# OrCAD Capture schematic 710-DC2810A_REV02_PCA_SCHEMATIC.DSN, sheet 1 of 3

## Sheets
1 LTM4673 PAGE1: size Custom; company: ANALOG DEVICES; note: DEMO BOARD BILL OF MATERIALS; note: QUAD OUTPUT DC/DC PSM µMODULE REGULATOR
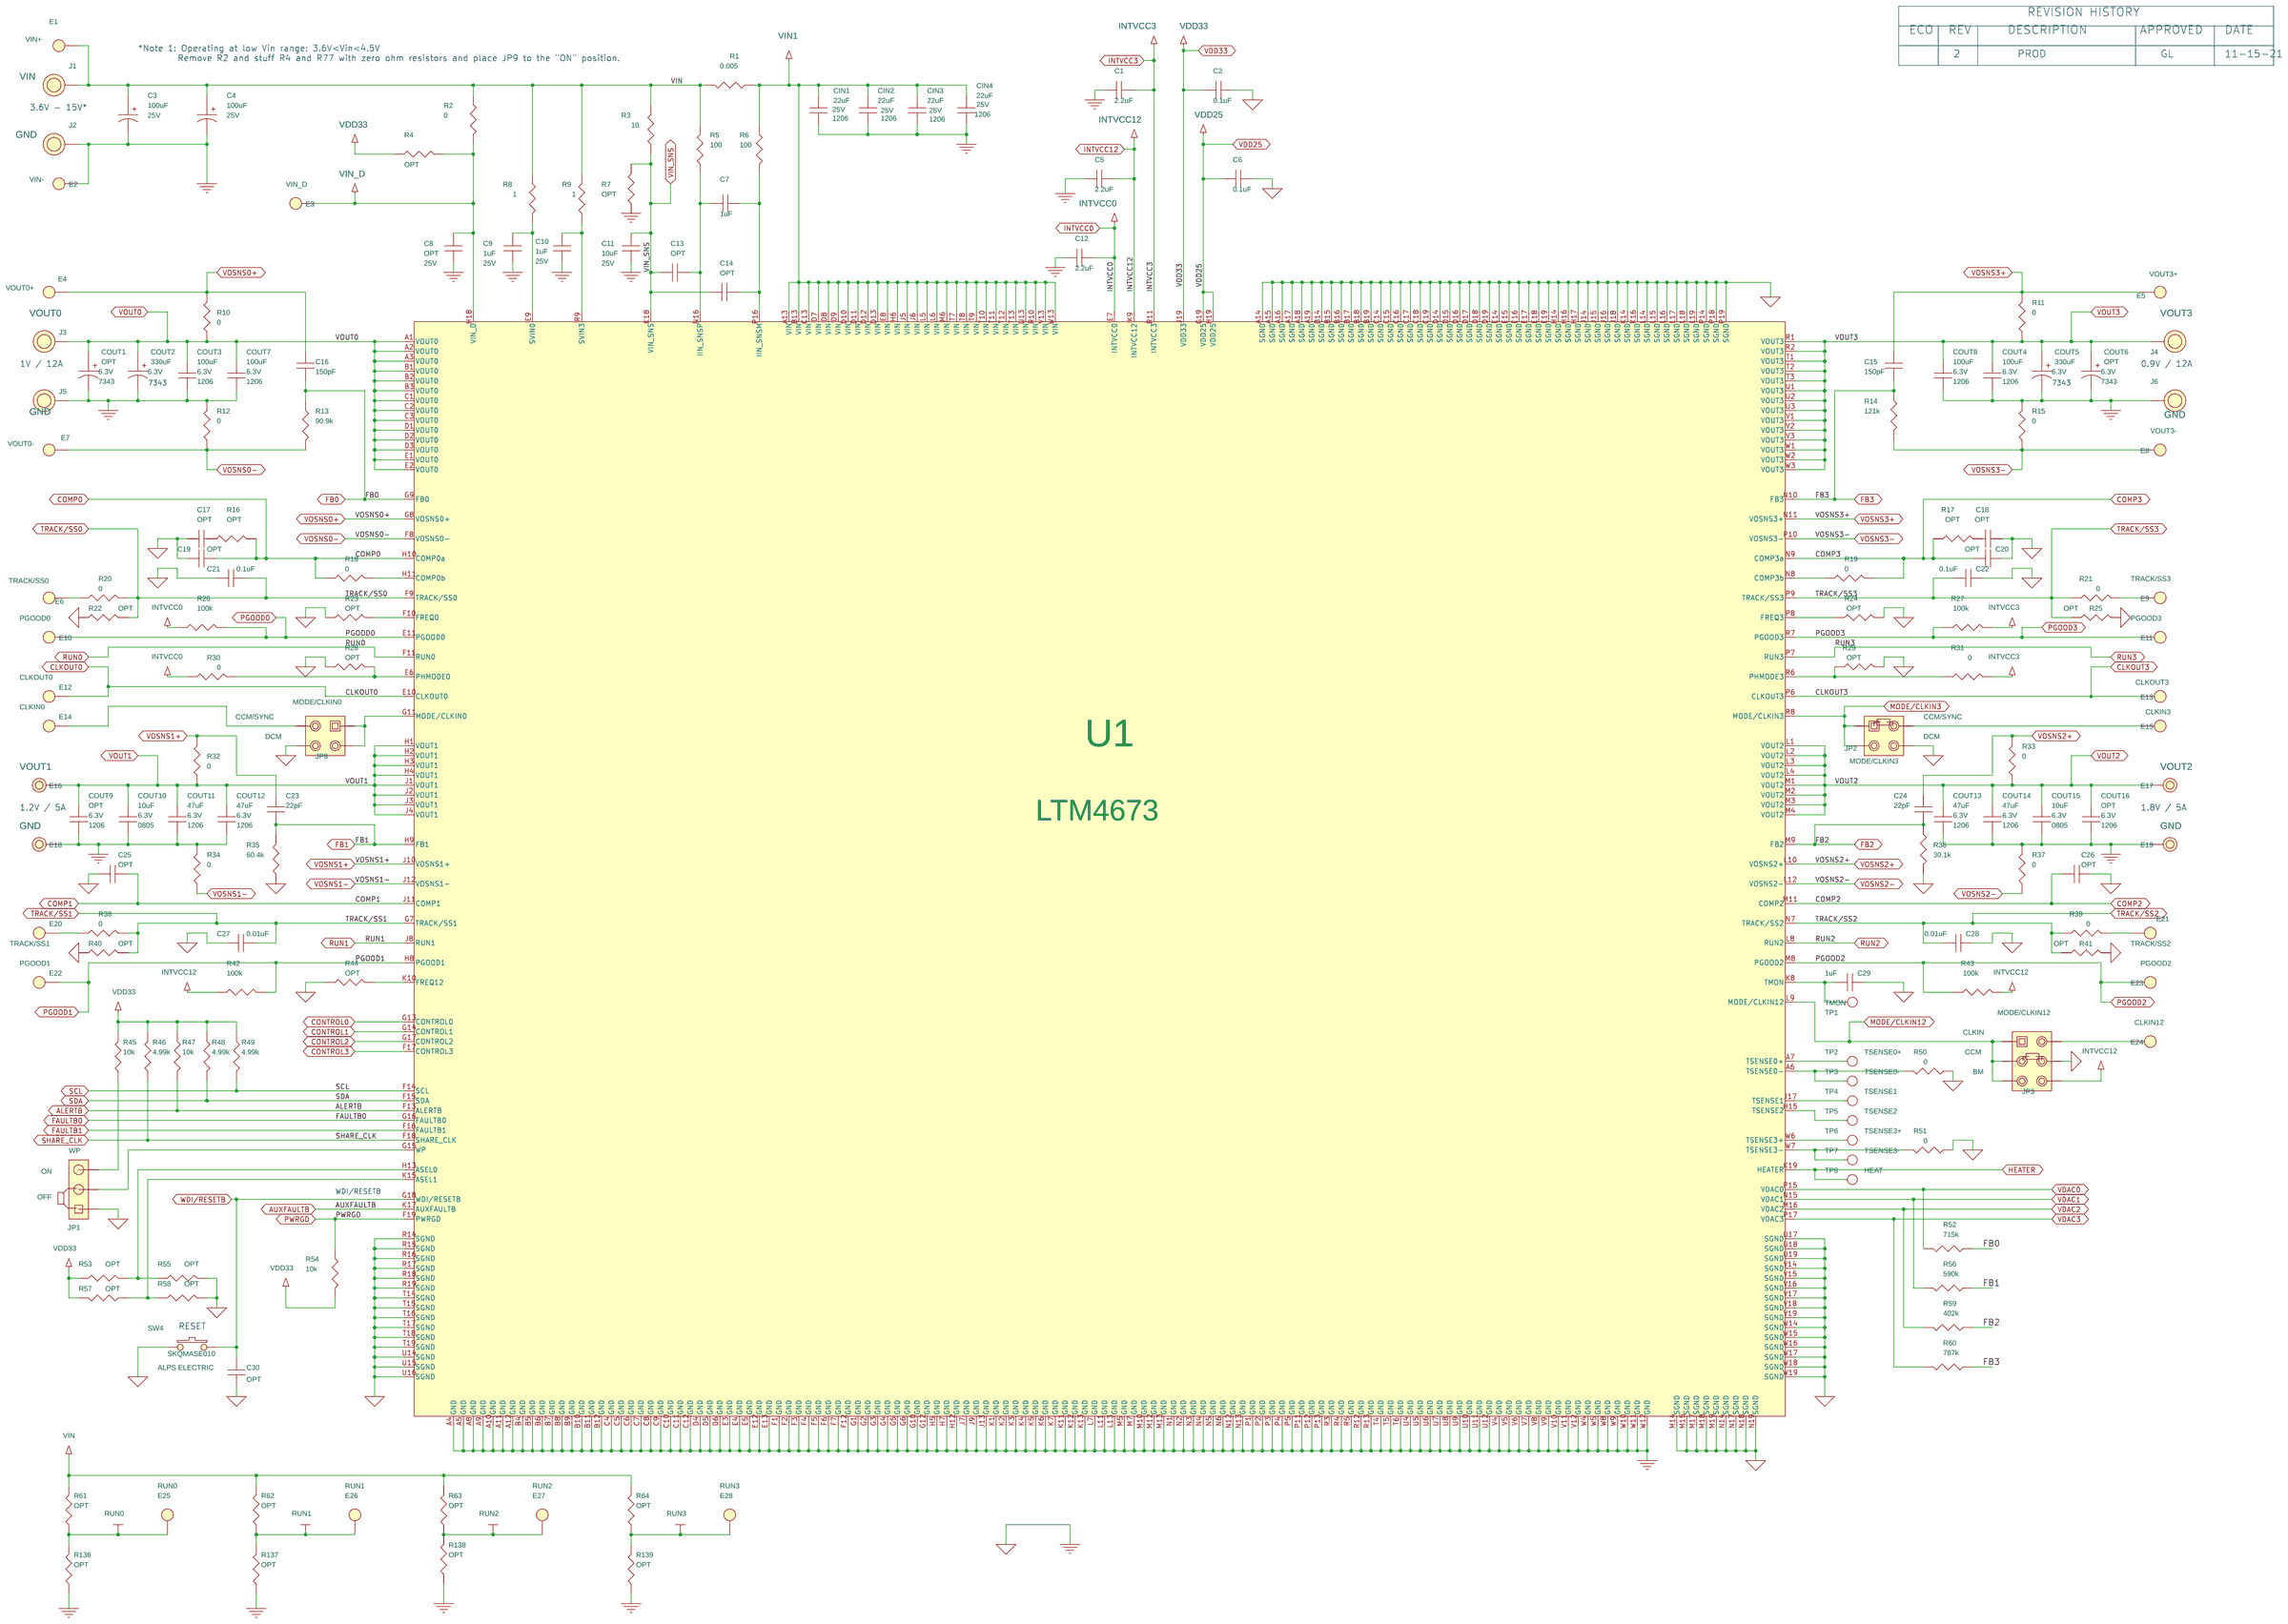
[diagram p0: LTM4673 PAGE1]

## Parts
C1  2.2uF  [CC0603N]
C2  0.1uF  [CC0603N]
C3  100uF  [PANASONIC_SVPF_8X6.9]
C4  100uF  [PANASONIC_SVPF_8X6.9]
C5  2.2uF  [CC0603N]
C6  0.1uF  [CC0603N]
C7  1uF  [CC0603N]
C8  OPT  [CC0603N]
C9  1uF  [CC0603N]
C10  1uF  [CC0603N]
C11  10uF  [CC0603N]
C12  2.2uF  [CC0603N]
C13  OPT  [CC0603N]
C14  OPT  [CC0603N]
C15  150pF  [CC0603N]
C16  150pF  [CC0603N]
C17  OPT  [CC0603N]
C18  OPT  [CC0603N]
C19  OPT  [CC0603N]
C20  OPT  [CC0603N]
C21  0.1uF  [CC0603N]
C22  0.1uF  [CC0603N]
C23  22pF  [CC0603N]
C24  22pF  [CC0603N]
C25  OPT  [CC0603N]
C26  OPT  [CC0603N]
C27  0.01uF  [CC0603N]
C28  0.01uF  [CC0603N]
C29  1uF  [CC0603N]
C30  OPT  [CC0603N]
CIN1  22uF  [CC1206N]
CIN2  22uF  [CC1206N]
CIN3  22uF  [CC1206N]
CIN4  22uF  [CC1206N]
COUT1  OPT  [CAPMP7343N]
COUT2  330uF  [CAPMP7343N]
COUT3  100uF  [CC1206N]
COUT4  100uF  [CC1206N]
COUT5  330uF  [CAPMP7343N]
COUT6  OPT  [CAPMP7343N]
COUT7  100uF  [CC1206N]
COUT8  100uF  [CC1206N]
COUT9  OPT  [CC1206N]
COUT10  10uF  [CC0805N]
COUT11  47uF  [CC1206N]
COUT12  47uF  [CC1206N]
COUT13  47uF  [CC1206N]
COUT14  47uF  [CC1206N]
COUT15  10uF  [CC0805N]
COUT16  OPT  [CC1206N]
E1  TEST POINT  [MILLMAX2308]
E2  TEST POINT  [MILLMAX2308]
E3  TEST POINT  [MILLMAX2308]
E4  TEST POINT  [MILLMAX2308]
E5  TEST POINT  [MILLMAX2308]
E6  TEST POINT  [MILLMAX2308]
E7  TEST POINT  [MILLMAX2308]
E8  TEST POINT  [MILLMAX2308]
E9  TEST POINT  [MILLMAX2308]
E10  TEST POINT  [MILLMAX2308]
E11  TEST POINT  [MILLMAX2308]
E12  TEST POINT  [MILLMAX2308]
E13  TEST POINT  [MILLMAX2308]
E14  TEST POINT  [MILLMAX2308]
E15  TEST POINT  [MILLMAX2308]
E16  TEST POINT  [MILLMAX2501]
E17  TEST POINT  [MILLMAX2501]
E18  TEST POINT  [MILLMAX2501]
E19  TEST POINT  [MILLMAX2501]
E20  TEST POINT  [MILLMAX2308]
E21  TEST POINT  [MILLMAX2308]
E22  TEST POINT  [MILLMAX2308]
E23  TEST POINT  [MILLMAX2308]
E24  TEST POINT  [MILLMAX2308]
E25  TEST POINT  [MILLMAX2308]
E26  TEST POINT  [MILLMAX2308]
E27  TEST POINT  [MILLMAX2308]
E28  TEST POINT  [MILLMAX2308]
J1  BANANA JACK  [KEY-575-4]
J2  BANANA JACK  [KEY-575-4]
J3  BANANA JACK  [KEY-575-4]
J4  BANANA JACK  [KEY-575-4]
J5  BANANA JACK  [KEY-575-4]
J6  BANANA JACK  [KEY-575-4]
JP1  HDR.  [HD1X3-079]
JP2  HDR  [HD2X2-079]
JP3  HDR.  [HD2X3-079]
JP8  HDR  [HD2X2-079]
R1  0.005  [PANASONIC-ERJMS4H]
R2  0  [CR0603N]
R3  10  [CR0603N]
R4  OPT  [CR0603N]
R5  100  [CR0603N]
R6  100  [CR0603N]
R7  OPT  [CR0603N]
R8  1  [CR0603N]
R9  1  [CR0603N]
R10  0  [CR0603N]
R11  0  [CR0603N]
R12  0  [CR0603N]
R13  90.9k  [CR0603N]
R14  121k  [CR0603N]
R15  0  [CR0603N]
R16  OPT  [CR0603N]
R17  OPT  [CR0603N]
R18  0  [CR0603N]
R19  0  [CR0603N]
R20  0  [CR0603N]
R21  0  [CR0603N]
R22  OPT  [CR0603N]
R23  OPT  [CR0603N]
R24  OPT  [CR0603N]
R25  OPT  [CR0603N]
R26  100k  [CR0603N]
R27  100k  [CR0603N]
R28  OPT  [CR0603N]
R29  OPT  [CR0603N]
R30  0  [CR0603N]
R31  0  [CR0603N]
R32  0  [CR0603N]
R33  0  [CR0603N]
R34  0  [CR0603N]
R35  60.4k  [CR0603N]
R36  30.1k  [CR0603N]
R37  0  [CR0603N]
R38  0  [CR0603N]
R39  0  [CR0603N]
R40  OPT  [CR0603N]
R41  OPT  [CR0603N]
R42  100k  [CR0603N]
R43  100k  [CR0603N]
R44  OPT  [CR0603N]
R45  10k  [CR0603N]
R46  4.99k  [CR0603N]
R47  10k  [CR0603N]
R48  4.99k  [CR0603N]
R49  4.99k  [CR0603N]
R50  0  [CR0603N]
R51  0  [CR0603N]
R52  715k  [CR0603N]
R53  OPT  [CR0603N]
R54  10k  [CR0603N]
R55  OPT  [CR0603N]
R56  590k  [CR0603N]
R57  OPT  [CR0603N]
R58  OPT  [CR0603N]
R59  402k  [CR0603N]
R60  787k  [CR0603N]
R61  OPT  [CR0603N]
R62  OPT  [CR0603N]
R63  OPT  [CR0603N]
R64  OPT  [CR0603N]
R136  OPT  [CR0603N]
R137  OPT  [CR0603N]
R138  OPT  [CR0603N]
R139  OPT  [CR0603N]
SW4  SPST  [ALPS-SKQMASE010]
TP1  TMON  [PAD]
TP2  TSENSE0+  [PAD]
TP3  TSENSE0-  [PAD]
TP4  TSENSE1  [PAD]
TP5  TSENSE2  [PAD]
TP6  TSENSE3+  [PAD]
TP7  TSENSE3-  [PAD]
TP8  HEAT  [PAD]
U1  LTM4673  [LTC-BGA-361-1601]
XJP1  SHUNT
XJP2  SHUNT
XJP3  SHUNT
XJP8  SHUNT

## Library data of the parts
C1 C5 C12 = CAP: CAP.,2.2uF,X5R,6.3V,10%,0603; CLASS: DISCRETE; Dielectric Type: X5R; FPLIST: CC0603N,CC0603L,CC0603M; Inventory Qty: 5538; Manufacturer: AVX; Manufacturer PN: 06036D225KAT2A; PART_NUMBER: 150-0116; Package Size: 0603; Rated Voltage: 6.3V; Tolerance: 10%
C2 C6 C21 C22 = CAP: CAP.,0.1uF,X7R,16V,10%,0603,FLEXITERM; CLASS: DISCRETE; Dielectric Type: X7R; FPLIST: CC0603N,CC0603L,CC0603M; Inventory Qty: 23721; Manufacturer: AVX; Manufacturer PN: 0603YC104KAZ2A; PART_NUMBER: 150-0165; Package Size: 0603; Rated Voltage: 16V; Tolerance: 10%
C3 C4 = CAP_P_ALT: CAP.,100uF,ALUM. OS-CON,25V,20%,8x6.9mm SMD, E7,SVPF Series; CLASS: DISCRETE; Component: cap; Dielectric Type: ALUM. OS-CON; Inventory Qty: 6; Manufacturer: PANASONIC; Manufacturer PN: 25SVPF100M; PART_NUMBER: 150-2546; Package Size: 8x6.9mm SMD, E7; Rated Voltage: 25V; Tolerance: 20%; UserField01: SVPF Series
C7 C9 C10 = CAP: CAP.,1uF,X7R,25V,10%,0603,AEC-Q200; CLASS: DISCRETE; Dielectric Type: X7R; FPLIST: CC0603N,CC0603L,CC0603M; Inventory Qty: 14407; Manufacturer: MURATA; Manufacturer PN: GCM188R71E105KA64D; PART_NUMBER: 150-0291; Package Size: 0603; Rated Voltage: 25V; Tolerance: 10%
C8 = CAP: CAP., OPTION, 0603; CLASS: DISCRETE; FPLIST: CC0603N,CC0603L,CC0603M; PART_FIELD_01: 25V; PART_NUMBER: 150-3038; Package Size: 0603; Package Type: SMD; UserField01: OPTION
C11 = CAP: CAP.,10uF,X5R,25V,20%,0603,NO SUBS. ALLOWED; CLASS: DISCRETE; Dielectric Type: X5R; FPLIST: CC0603N,CC0603L,CC0603M; Inventory Qty: 18160; Manufacturer: MURATA; Manufacturer PN: GRM188R61E106MA73D; PART_NUMBER: 150-2347; Package Size: 0603; Rated Voltage: 25V; Tolerance: 20%; UserField01: NO SUBS. ALLOWED
C13 C14 C17-C20 C25 C26 C30 = CAP: CAP., OPTION, 0603; CLASS: DISCRETE; FPLIST: CC0603N,CC0603L,CC0603M; PART_NUMBER: 150-3038; Package Size: 0603; Package Type: SMD; UserField01: OPTION
C15 C16 = CAP: CAP.,150pF,X7R,50V,10%,0603; CLASS: DISCRETE; Dielectric Type: X7R; FPLIST: CC0603N,CC0603L,CC0603M; Inventory Qty: 17421; Manufacturer: AVX; Manufacturer PN: 06035C151KAT2A; PART_NUMBER: 150-2627; Package Size: 0603; Rated Voltage: 50V; Tolerance: 10%; UserField01: OPTION
C23 = CAP: CAP.,22pF,C0G,50V,5%,0603; CLASS: DISCRETE; Dielectric Type: C0G; FPLIST: CC0603N,CC0603L,CC0603M; Inventory Qty: 11643; Manufacturer: AVX; Manufacturer PN: 06035A220JAT2A; PART_NUMBER: 150-2248; Package Size: 0603; Rated Voltage: 50V; Tolerance: 5%
C24 = CAP: CAP.,22pF,C0G,50V,5%,0603; CLASS: DISCRETE; Dielectric Type: C0G; FPLIST: CC0603N,CC0603L,CC0603M; Inventory Qty: 11643; Manufacturer: AVX; Manufacturer PN: 06035A220JAT2A; PART_NUMBER: 150-2248; Package Size: 0603; Rated Voltage: 50V; Tolerance: 5%; UserField01: OPTION
C27 C28 = CAP: CAP.,0.01uF,X7R,16V,10%,0603; CLASS: DISCRETE; Dielectric Type: X7R; FPLIST: CC0603N,CC0603L,CC0603M; Inventory Qty: 69461; Manufacturer: AVX; Manufacturer PN: 0603YC103KAT2A; PART_NUMBER: 150-0038; Package Size: 0603; Rated Voltage: 16V; Tolerance: 10%
C29 = CAP: CAP.,1uF,X7R,16V,10%,0603; CLASS: DISCRETE; Dielectric Type: X7R; FPLIST: CC0603N,CC0603L,CC0603M; Inventory Qty: 29507; Manufacturer: KEMET; Manufacturer PN: C0603C105K4RAC7867; PART_NUMBER: 150-0179; Package Size: 0603; Rated Voltage: 16V; Tolerance: 10%
CIN1-CIN4 = CAP: CAP.,22uF,X5R,25V,10%,1206; CLASS: DISCRETE; Dielectric Type: X5R; FPLIST: CC1206N,CC1206L,CC1206M; Inventory Qty: 8019; Manufacturer: AVX; Manufacturer PN: 12063D226KAT2A; PART_NUMBER: 150-0253; Package Size: 1206; Rated Voltage: 25V; Tolerance: 10%
COUT1 COUT6 = CAP_P_ALT: CAP., OPTION, 7343; BOM Notes: COUT1,COUT6=6.3V; CLASS: DISCRETE; FPLIST: CAPMP7343N,CAPMP7343L,CAPMP7343M; PART_FIELD_01: 6.3V; PART_NUMBER: 150-0067; Package Size: 7343; Package Type: SMD
COUT2 COUT5 = CAP_P_ALT: CAP.,330uF,TANT. POSCAP,6.3V,20%,7343,10mOHMS, TPF, NO SUBS. ALLOWED; CLASS: DISCRETE; Dielectric Type: TANT. POSCAP; FPLIST: CAPMP7343N,CAPMP7343L,CAPMP7343M; Inventory Qty: 4336; Manufacturer: PANASONIC; Manufacturer PN: 6TPF330M9L; PART_NUMBER: 150-3034; Package Size: 7343; Rated Voltage: 6.3V; Tolerance: 20%
COUT3 COUT4 COUT7 COUT8 = CAP: CAP.,100uF,X5R,6.3V,10%,1206; CLASS: DISCRETE; Dielectric Type: X5R; FPLIST: CC1206N,CC1206L,CC1206M; Inventory Qty: 6880; Manufacturer: MURATA; Manufacturer PN: GRM31CR60J107KE39L; PART_NUMBER: 150-2327; Package Size: 1206; Rated Voltage: 6.3V; Tolerance: 10%
COUT9 COUT16 = CAP: CAP., OPTION, 1206; BOM Notes: COUT9,COUT16=6.3V; CLASS: DISCRETE; FPLIST: CC1206N,CC1206L,CC1206M; PART_FIELD_01: 6.3V; PART_NUMBER: 150-3160; Package Size: 1206; Package Type: SMD
COUT10 COUT15 = CAP: CAP.,10uF,X5R,6.3V,10%,0805; CLASS: DISCRETE; Dielectric Type: X5R; FPLIST: CC0805N,CC0805L,CC0805M; Inventory Qty: 29564; Manufacturer: AVX; Manufacturer PN: 08056D106KAT2A; PART_NUMBER: 150-0079; Package Size: 0805; Rated Voltage: 6.3V; Tolerance: 10%
COUT11-COUT14 = CAP: CAP.,47uF,X5R,6.3V,20%,1206; CLASS: DISCRETE; Dielectric Type: X5R; FPLIST: CC1206N,CC1206L,CC1206M; Inventory Qty: 7374; Manufacturer: MURATA; Manufacturer PN: GRM31CR60J476ME19L; PART_NUMBER: 150-3443; Package Size: 1206; Rated Voltage: 6.3V; Tolerance: 20%
E1 = TEST_POINT_.156_MILL-MAX_2308: TEST POINT,TURRET,0.064" MTG. HOLE,PCB 0.062" THK; CLASS: IO; Inventory Qty: 767848; Manufacturer: MILL-MAX; Manufacturer PN: 2308-2-00-80-00-00-07-0; PART_FIELD_01: VIN+; PART_NUMBER: 260-0004
E2 = TEST_POINT_.156_MILL-MAX_2308: TEST POINT,TURRET,0.064" MTG. HOLE,PCB 0.062" THK; CLASS: IO; Inventory Qty: 767848; Manufacturer: MILL-MAX; Manufacturer PN: 2308-2-00-80-00-00-07-0; PART_FIELD_01: VIN-; PART_NUMBER: 260-0004
E3 = TEST_POINT_.156_MILL-MAX_2308: TEST POINT,TURRET,0.064" MTG. HOLE,PCB 0.062" THK; CLASS: IO; Inventory Qty: 767848; Manufacturer: MILL-MAX; Manufacturer PN: 2308-2-00-80-00-00-07-0; PART_FIELD_01: VIN_D; PART_NUMBER: 260-0004
E4 = TEST_POINT_.156_MILL-MAX_2308: TEST POINT,TURRET,0.064" MTG. HOLE,PCB 0.062" THK; CLASS: IO; Inventory Qty: 767848; Manufacturer: MILL-MAX; Manufacturer PN: 2308-2-00-80-00-00-07-0; PART_FIELD_01: VOUT0+; PART_NUMBER: 260-0004
E5 = TEST_POINT_.156_MILL-MAX_2308: TEST POINT,TURRET,0.064" MTG. HOLE,PCB 0.062" THK; CLASS: IO; Inventory Qty: 767848; Manufacturer: MILL-MAX; Manufacturer PN: 2308-2-00-80-00-00-07-0; PART_FIELD_01: VOUT3+; PART_NUMBER: 260-0004
E6 = TEST_POINT_.156_MILL-MAX_2308: TEST POINT,TURRET,0.064" MTG. HOLE,PCB 0.062" THK; CLASS: IO; Inventory Qty: 767848; Manufacturer: MILL-MAX; Manufacturer PN: 2308-2-00-80-00-00-07-0; PART_FIELD_01: TRACK/SS0; PART_NUMBER: 260-0004
E7 = TEST_POINT_.156_MILL-MAX_2308: TEST POINT,TURRET,0.064" MTG. HOLE,PCB 0.062" THK; CLASS: IO; Inventory Qty: 767848; Manufacturer: MILL-MAX; Manufacturer PN: 2308-2-00-80-00-00-07-0; PART_FIELD_01: VOUT0-; PART_NUMBER: 260-0004
E8 = TEST_POINT_.156_MILL-MAX_2308: TEST POINT,TURRET,0.064" MTG. HOLE,PCB 0.062" THK; CLASS: IO; Inventory Qty: 767848; Manufacturer: MILL-MAX; Manufacturer PN: 2308-2-00-80-00-00-07-0; PART_FIELD_01: VOUT3-; PART_NUMBER: 260-0004
E9 = TEST_POINT_.156_MILL-MAX_2308: TEST POINT,TURRET,0.064" MTG. HOLE,PCB 0.062" THK; CLASS: IO; Inventory Qty: 767848; Manufacturer: MILL-MAX; Manufacturer PN: 2308-2-00-80-00-00-07-0; PART_FIELD_01: TRACK/SS3; PART_NUMBER: 260-0004
E10 = TEST_POINT_.156_MILL-MAX_2308: TEST POINT,TURRET,0.064" MTG. HOLE,PCB 0.062" THK; CLASS: IO; Inventory Qty: 767848; Manufacturer: MILL-MAX; Manufacturer PN: 2308-2-00-80-00-00-07-0; PART_FIELD_01: PGOOD0; PART_NUMBER: 260-0004
E11 = TEST_POINT_.156_MILL-MAX_2308: TEST POINT,TURRET,0.064" MTG. HOLE,PCB 0.062" THK; CLASS: IO; Inventory Qty: 767848; Manufacturer: MILL-MAX; Manufacturer PN: 2308-2-00-80-00-00-07-0; PART_FIELD_01: PGOOD3; PART_NUMBER: 260-0004
E12 = TEST_POINT_.156_MILL-MAX_2308: TEST POINT,TURRET,0.064" MTG. HOLE,PCB 0.062" THK; CLASS: IO; Inventory Qty: 767848; Manufacturer: MILL-MAX; Manufacturer PN: 2308-2-00-80-00-00-07-0; PART_FIELD_01: CLKOUT0; PART_NUMBER: 260-0004
E13 = TEST_POINT_.156_MILL-MAX_2308: TEST POINT,TURRET,0.064" MTG. HOLE,PCB 0.062" THK; CLASS: IO; Inventory Qty: 767848; Manufacturer: MILL-MAX; Manufacturer PN: 2308-2-00-80-00-00-07-0; PART_FIELD_01: CLKOUT3; PART_NUMBER: 260-0004
E14 = TEST_POINT_.156_MILL-MAX_2308: TEST POINT,TURRET,0.064" MTG. HOLE,PCB 0.062" THK; CLASS: IO; Inventory Qty: 767848; Manufacturer: MILL-MAX; Manufacturer PN: 2308-2-00-80-00-00-07-0; PART_FIELD_01: CLKIN0; PART_NUMBER: 260-0004
E15 = TEST_POINT_.156_MILL-MAX_2308: TEST POINT,TURRET,0.064" MTG. HOLE,PCB 0.062" THK; CLASS: IO; Inventory Qty: 767848; Manufacturer: MILL-MAX; Manufacturer PN: 2308-2-00-80-00-00-07-0; PART_FIELD_01: CLKIN3; PART_NUMBER: 260-0004
E16 = TESTPOINT_.219_MILL-MAX_2501: TEST POINT,TURRET,0.094" MTG. HOLE,PCB 0.062" THK; CLASS: IO; Inventory Qty: 467396; Manufacturer: MILL-MAX; Manufacturer PN: 2501-2-00-80-00-00-07-0; PART_FIELD_01: VOUT1; PART_NUMBER: 260-0003
E17 = TESTPOINT_.219_MILL-MAX_2501: TEST POINT,TURRET,0.094" MTG. HOLE,PCB 0.062" THK; CLASS: IO; Inventory Qty: 467396; Manufacturer: MILL-MAX; Manufacturer PN: 2501-2-00-80-00-00-07-0; PART_FIELD_01: VOUT2; PART_NUMBER: 260-0003
E18 E19 = TESTPOINT_.219_MILL-MAX_2501: TEST POINT,TURRET,0.094" MTG. HOLE,PCB 0.062" THK; CLASS: IO; Inventory Qty: 467396; Manufacturer: MILL-MAX; Manufacturer PN: 2501-2-00-80-00-00-07-0; PART_FIELD_01: GND; PART_NUMBER: 260-0003
E20 = TEST_POINT_.156_MILL-MAX_2308: TEST POINT,TURRET,0.064" MTG. HOLE,PCB 0.062" THK; CLASS: IO; Inventory Qty: 767848; Manufacturer: MILL-MAX; Manufacturer PN: 2308-2-00-80-00-00-07-0; PART_FIELD_01: TRACK/SS1; PART_NUMBER: 260-0004
E21 = TEST_POINT_.156_MILL-MAX_2308: TEST POINT,TURRET,0.064" MTG. HOLE,PCB 0.062" THK; CLASS: IO; Inventory Qty: 767848; Manufacturer: MILL-MAX; Manufacturer PN: 2308-2-00-80-00-00-07-0; PART_FIELD_01: TRACK/SS2; PART_NUMBER: 260-0004
E22 = TEST_POINT_.156_MILL-MAX_2308: TEST POINT,TURRET,0.064" MTG. HOLE,PCB 0.062" THK; CLASS: IO; Inventory Qty: 767848; Manufacturer: MILL-MAX; Manufacturer PN: 2308-2-00-80-00-00-07-0; PART_FIELD_01: PGOOD1; PART_NUMBER: 260-0004
E23 = TEST_POINT_.156_MILL-MAX_2308: TEST POINT,TURRET,0.064" MTG. HOLE,PCB 0.062" THK; CLASS: IO; Inventory Qty: 767848; Manufacturer: MILL-MAX; Manufacturer PN: 2308-2-00-80-00-00-07-0; PART_FIELD_01: PGOOD2; PART_NUMBER: 260-0004
E24 = TEST_POINT_.156_MILL-MAX_2308: TEST POINT,TURRET,0.064" MTG. HOLE,PCB 0.062" THK; CLASS: IO; Inventory Qty: 767848; Manufacturer: MILL-MAX; Manufacturer PN: 2308-2-00-80-00-00-07-0; PART_FIELD_01: CLKIN12; PART_NUMBER: 260-0004
E25 = TEST_POINT_.156_MILL-MAX_2308: TEST POINT,TURRET,0.064" MTG. HOLE,PCB 0.062" THK; CLASS: IO; Inventory Qty: 767848; Manufacturer: MILL-MAX; Manufacturer PN: 2308-2-00-80-00-00-07-0; PART_FIELD_01: RUN0; PART_NUMBER: 260-0004
E26 = TEST_POINT_.156_MILL-MAX_2308: TEST POINT,TURRET,0.064" MTG. HOLE,PCB 0.062" THK; CLASS: IO; Inventory Qty: 767848; Manufacturer: MILL-MAX; Manufacturer PN: 2308-2-00-80-00-00-07-0; PART_FIELD_01: RUN1; PART_NUMBER: 260-0004
E27 = TEST_POINT_.156_MILL-MAX_2308: TEST POINT,TURRET,0.064" MTG. HOLE,PCB 0.062" THK; CLASS: IO; Inventory Qty: 767848; Manufacturer: MILL-MAX; Manufacturer PN: 2308-2-00-80-00-00-07-0; PART_FIELD_01: RUN2; PART_NUMBER: 260-0004
E28 = TEST_POINT_.156_MILL-MAX_2308: TEST POINT,TURRET,0.064" MTG. HOLE,PCB 0.062" THK; CLASS: IO; Inventory Qty: 767848; Manufacturer: MILL-MAX; Manufacturer PN: 2308-2-00-80-00-00-07-0; PART_FIELD_01: RUN3; PART_NUMBER: 260-0004
J1 = BANANA_KEYSTONE-575-4_B: CONN.,BANANA JACK,FEMALE,THT,NON-INSULATED,SWAGE,0.218"; CLASS: IO; Inventory Qty: 199005; Manufacturer: KEYSTONE; Manufacturer PN: 575-4; PART_FIELD_01: VIN; PART_NUMBER: 250-0428
J2 J5 J6 = BANANA_KEYSTONE-575-4_B: CONN.,BANANA JACK,FEMALE,THT,NON-INSULATED,SWAGE,0.218"; CLASS: IO; Inventory Qty: 199005; Manufacturer: KEYSTONE; Manufacturer PN: 575-4; PART_FIELD_01: GND; PART_NUMBER: 250-0428
J3 = BANANA_KEYSTONE-575-4_B: CONN.,BANANA JACK,FEMALE,THT,NON-INSULATED,SWAGE,0.218"; CLASS: IO; Inventory Qty: 199005; Manufacturer: KEYSTONE; Manufacturer PN: 575-4; PART_FIELD_01: VOUT0; PART_NUMBER: 250-0428
J4 = BANANA_KEYSTONE-575-4_B: CONN.,BANANA JACK,FEMALE,THT,NON-INSULATED,SWAGE,0.218"; CLASS: IO; Inventory Qty: 199005; Manufacturer: KEYSTONE; Manufacturer PN: 575-4; PART_FIELD_01: VOUT3; PART_NUMBER: 250-0428
JP1 = 1X3_B: CONN.,HDR.,MALE,1x3,2mm,THT, STR,NO SUBS. ALLOWED; 11th Part Field: ON; 12th Part Field: WP; 9th Part Field: OFF; CLASS: IO; FPLIST: HD1X3-079,JP3X1/079; Inventory Qty: 9292; Manufacturer: SAMTEC; Manufacturer PN: TMM-103-02-L-S; PART_NUMBER: 250-0638
JP2 = HDR2X2_ALT1: CONN.,HDR,MALE,2x2,2mm,VERT, STR, THT,10u" Au; 9th Part Field: MODE/CLKIN3; CLASS: IO; Inventory Qty: 21882; Manufacturer: SAMTEC; Manufacturer PN: TMM-102-02-L-D; PART_FIELD_01: CCM/SYNC; PART_FIELD_02: DCM; PART_NUMBER: 250-0424
JP3 = HDR2X3_ALT1: CONN.,HDR.,MALE,2x3,2mm,VERT,STR,THT; 9th Part Field: MODE/CLKIN12; CLASS: IO; Inventory Qty: 25837; Manufacturer: SAMTEC; Manufacturer PN: TMM-103-02-L-D; PART_FIELD_01: CLKIN; PART_FIELD_02: CCM; PART_FIELD_03: BM; PART_NUMBER: 250-0423
JP8 = HDR2X2_ALT1: CONN.,HDR,MALE,2x2,2mm,VERT, STR, THT,10u" Au; 9th Part Field: MODE/CLKIN0; CLASS: IO; Inventory Qty: 21882; Manufacturer: SAMTEC; Manufacturer PN: TMM-102-02-L-D; PART_FIELD_01: CCM/SYNC; PART_FIELD_02: DCM; PART_NUMBER: 250-0424
R1 = RES: RES.,0.005 OHM,1%,3W,2512,METAL, SENSE, AEC-Q200; CLASS: DISCRETE; Inventory Qty: 3984; Label: 2; Manufacturer: PANASONIC; Manufacturer PN: ERJMS4HF5M0U; PART_NUMBER: 100-1027; Package Size: 2512; Rated Power: 3W; Temperature Coefficient: +/-75ppm; Tolerance: 1%
R2 = RES: RES.,0 OHM,1/10W,0603,AEC-Q200; CLASS: DISCRETE; Component: res; FPLIST: CR0603N,CR0603L,CR0603M; Inventory Qty: 601530; Label: <label>; Manufacturer: VISHAY; Manufacturer PN: CRCW06030000Z0EA; PART_NUMBER: 100-0009; Package Size: 0603; Rated Power: 1/10W
R3 = RES: RES.,10 OHMS,1%,1/10W,0603; CLASS: DISCRETE; Component: res; FPLIST: CR0603N,CR0603L,CR0603M; Inventory Qty: 149976; Label: <label>; Manufacturer: VISHAY; Manufacturer PN: CRCW060310R0FKEA; PART_NUMBER: 100-2306; Package Size: 0603; Rated Power: 1/10W; Temperature Coefficient: 100ppm/C; Tolerance: 1%
R4 R7 = RES: RES., OPTION, 0603; CLASS: DISCRETE; Component: res; FPLIST: CR0603N,CR0603L,CR0603M; Label: <label>; PART_NUMBER: 100-2374; Package Size: 0603
R5 R6 = RES: RES.,100 OHMS,1%,1/10W,0603,AEC-Q200; CLASS: DISCRETE; FPLIST: CR0603N,CR0603L,CR0603M; Inventory Qty: 73748; Manufacturer: PANASONIC; Manufacturer PN: ERJ3EKF1000V; PART_NUMBER: 100-2586; Package Size: 0603; Rated Power: 1/10W; Temperature Coefficient: 100ppm; Tolerance: 1%
R8 = RES: RES.,1 OHM,1%,1/10W,0603; CLASS: DISCRETE; FPLIST: CR0603N,CR0603L,CR0603M; Inventory Qty: 15800; Manufacturer: YAGEO; Manufacturer PN: RC0603FR-071RL; PART_NUMBER: 100-0163; Package Size: 0603; Rated Power: 1/10W; Temperature Coefficient: 200ppm/C; Tolerance: 1%
R9 = RES: RES.,1 OHM,1%,1/10W,0603; CLASS: DISCRETE; Component: res; FPLIST: CR0603N,CR0603L,CR0603M; Inventory Qty: 15800; Label: <label>; Manufacturer: YAGEO; Manufacturer PN: RC0603FR-071RL; PART_NUMBER: 100-0163; Package Size: 0603; Rated Power: 1/10W; Temperature Coefficient: 200ppm/C; Tolerance: 1%
R10 R11 R32 R33 = RES: RES.,0 OHM,1%,0603,AEC-Q200; CLASS: DISCRETE; FPLIST: CR0603N,CR0603L,CR0603M; Inventory Qty: 34245; Manufacturer: KOA SPEER; Manufacturer PN: RK73Z1JTTDD; PART_NUMBER: 100-0596; Package Size: 0603; Tolerance: 1%
R12 R15 R18-R21 R30 R31 R34 R38 R39 R50 R51 = RES: RES.,0 OHM,1/10W,0603,AEC-Q200; CLASS: DISCRETE; FPLIST: CR0603N,CR0603L,CR0603M; Inventory Qty: 601530; Manufacturer: VISHAY; Manufacturer PN: CRCW06030000Z0EA; PART_NUMBER: 100-0009; Package Size: 0603; Rated Power: 1/10W
R13 = RES: RES.,90.9k OHMS,1%,1/10W,0603,AEC-Q200; CLASS: DISCRETE; FPLIST: CR0603N,CR0603L,CR0603M; Inventory Qty: 76786; Manufacturer: VISHAY; Manufacturer PN: CRCW060390K9FKEA; PART_NUMBER: 100-2379; Package Size: 0603; Rated Power: 1/10W; Temperature Coefficient: 100ppm/C; Tolerance: 1%
R14 = RES: RES.,121k OHMS,1%,1/10W,0603; CLASS: DISCRETE; FPLIST: CR0603N,CR0603L,CR0603M; Inventory Qty: 17276; Manufacturer: NIC; Manufacturer PN: NRC06F1213TRF; PART_NUMBER: 100-2725; Package Size: 0603; Rated Power: 1/10W; Temperature Coefficient: 100ppm/C; Tolerance: 1%
R16 R17 R22-R25 R28 R29 R40 R41 R44 R53 R55 R57 R58 R61-R64 R136-R139 = RES: RES., OPTION, 0603; CLASS: DISCRETE; FPLIST: CR0603N,CR0603L,CR0603M; PART_NUMBER: 100-2374; Package Size: 0603
R26 R27 R42 R43 = RES: RES.,100k OHMS,1%,1/10W,0603; CLASS: DISCRETE; FPLIST: CR0603N,CR0603L,CR0603M; Inventory Qty: 71787; Manufacturer: STACKPOLE ELECTRONICS, INC.; Manufacturer PN: RMCF0603FG100K; PART_NUMBER: 100-0112; Package Size: 0603; Rated Power: 1/10W; Tolerance: 1%
R35 = RES: RES.,60.4k OHMS,1%,1/10W,0603; CLASS: DISCRETE; FPLIST: CR0603N,CR0603L,CR0603M; Inventory Qty: 30641; Manufacturer: NIC; Manufacturer PN: NRC06F6042TRF; PART_NUMBER: 100-2759; Package Size: 0603; Rated Power: 1/10W; Temperature Coefficient: 100ppm/C; Tolerance: 1%
R36 = RES: RES.,30.1k OHMS,0.1%,1/10W,0603,AEC-Q200; CLASS: DISCRETE; FPLIST: CR0603N,CR0603L,CR0603M; Inventory Qty: 0; Manufacturer: PANASONIC; Manufacturer PN: ERA-3AEB3012V; PART_NUMBER: 100-1830; Package Size: 0603; Rated Power: 1/10W; Temperature Coefficient: +/-25PPM; Tolerance: 0.1%
R37 = RES: RES.,10 OHMS,1%,1/10W,0603; CLASS: DISCRETE; FPLIST: CR0603N,CR0603L,CR0603M; Inventory Qty: 149976; Manufacturer: VISHAY; Manufacturer PN: CRCW060310R0FKEA; PART_NUMBER: 100-2306; Package Size: 0603; Rated Power: 1/10W; Temperature Coefficient: 100ppm/C; Tolerance: 1%
R45 R47 R54 = RES: RES.,10k OHMS,1%,1/10W,0603; CLASS: DISCRETE; FPLIST: CR0603N,CR0603L,CR0603M; Inventory Qty: 74893; Manufacturer: VISHAY; Manufacturer PN: CRCW060310K0FKEC; PART_NUMBER: 100-2532; Package Size: 0603; Rated Power: 1/10W; Temperature Coefficient: 100ppm/C; Tolerance: 1%
R46 R48 R49 = RES: RES.,4.99k OHMS,1%,1/10W,0603; CLASS: DISCRETE; FPLIST: CR0603N,CR0603L,CR0603M; Inventory Qty: 72747; Manufacturer: PANASONIC; Manufacturer PN: ERJ3EKF4991V; PART_NUMBER: 100-0121; Package Size: 0603; Rated Power: 1/10W; Temperature Coefficient: 100ppm/C; Tolerance: 1%
R52 = RES: RES.,715k,OHMS,1%,1/10W,0603; CLASS: DISCRETE; FPLIST: CR0603N,CR0603L,CR0603M; Manufacturer: YAGEO AMERICA CORPORATION; Manufacturer PN: RC0603FR-07715KL; PART_NUMBER: TMP-7860; Package Size: 0603; Rated Power: 1/10W; Tolerance: 1%
R56 = RES: RES.,590k OHMS,1%,1/10W,0603; CLASS: DISCRETE; FPLIST: CR0603N,CR0603L,CR0603M; Inventory Qty: 0; Manufacturer: PANASONIC; Manufacturer PN: ERJ3EKF5903V; PART_NUMBER: 100-0181; Package Size: 0603; Rated Power: 1/10W; Temperature Coefficient: 100ppm/C; Tolerance: 1%
R59 = RES: RES.,402k OHMS,1%,1/10W,0603; CLASS: DISCRETE; FPLIST: CR0603N,CR0603L,CR0603M; Inventory Qty: 0; Manufacturer: YAGEO; Manufacturer PN: RC0603FR-07402KL; PART_NUMBER: 100-0155; Package Size: 0603; Rated Power: 1/10W; Temperature Coefficient: 100ppm/C; Tolerance: 1%
R60 = RES: RES.,787k OHMS,0.1%,1/10W,0603,AEC-Q200; CLASS: DISCRETE; FPLIST: CR0603N,CR0603L,CR0603M; Inventory Qty: 0; Manufacturer: KOA SPEER; Manufacturer PN: RN73H1JTTD7873B25; PART_NUMBER: 100-1834; Package Size: 0603; Rated Power: 1/10W; Temperature Coefficient: +/-25PPM; Tolerance: 0.1%
SW4 = SW-PB-SPST-MC: SWITCH,TACT.,SPST,0.05A,12VDC,VERT, 6x3.5mm SMD,BLK, TOP PUSH; CLASS: DISCRETE; Inventory Qty: 484; Manufacturer: ALPS ELECTRIC; Manufacturer PN: SKQMASE010; PART_NUMBER: 430-0081
TP1-TP8 = E-100SMT
U1 = LTM4673-BGA_11: IC,QUAD OUTPUT DC/D uMODULE REG.,BGA; CLASS: IC; Inventory Qty: 0; Manufacturer: LINEAR TECH.; Manufacturer PN: LTM4673IY#PBF; PART_NUMBER: LTM4673IY#PBF; Package Type: BGA
XJP1 = SHUNT_2MM: CONN.,SHUNT,FEMALE,2-POS,2mm; CLASS: IO; Inventory Qty: 97153; Manufacturer: SAMTEC; Manufacturer PN: 2SN-BK-G; PART_NUMBER: 250-0419
XJP2 XJP3 XJP8 = SHUNT_2MM_C: CONN.,SHUNT,FEMALE,2-POS,2mm; CLASS: IO; Inventory Qty: 97153; Manufacturer: SAMTEC; Manufacturer PN: 2SN-BK-G; PART_NUMBER: 250-0419

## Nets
GND_POWER: C1.1 C3.2 C4.2 C5.1 C8.1 C9.1 C10.1 C11.1 C12.1 CIN1.1 CIN2.1 CIN3.1 CIN4.1 COUT1.2 COUT2.2 COUT3.2 COUT4.2 COUT5.2 COUT6.2 COUT7.2 COUT8.2 COUT9.2 COUT10.2 COUT11.2 COUT12.2 COUT13.2 COUT14.2 COUT15.2 COUT16.2 E2.1(A) E18.1 E19.1 J2.1 J5.1 J6.1 R7.1 R12.1 R15.1 R34.1 R37.1 R136.1 R137.1 R138.1 R139.1 U1.A4(GND) U1.A5(GND) U1.A8(GND) U1.A9(GND) U1.A10(GND) U1.A11(GND) U1.A12(GND) U1.B4(GND) U1.B5(GND) U1.B6(GND) U1.B7(GND) U1.B8(GND) U1.B9(GND) U1.B10(GND) U1.B11(GND) U1.B12(GND) U1.C4(GND) U1.C5(GND) U1.C6(GND) U1.C7(GND) U1.C8(GND) U1.C9(GND) U1.C10(GND) U1.C11(GND) U1.C12(GND) U1.D4(GND) U1.D5(GND) U1.D6(GND) U1.E3(GND) U1.E4(GND) U1.E5(GND) U1.E12(GND) U1.E13(GND) U1.F1(GND) U1.F2(GND) U1.F3(GND) U1.F4(GND) U1.F5(GND) U1.F6(GND) U1.F7(GND) U1.F12(GND) U1.G1(GND) U1.G2(GND) U1.G3(GND) U1.G4(GND) U1.G5(GND) U1.G6(GND) U1.G10(GND) U1.G12(GND) U1.H5(GND) U1.H7(GND) U1.H12(GND) U1.J7(GND) U1.J9(GND) U1.J13(GND) U1.K1(GND) U1.K2(GND) U1.K3(GND) U1.K4(GND) U1.K5(GND) U1.K6(GND) U1.K7(GND) U1.K11(GND) U1.K12(GND) U1.K13(GND) U1.L7(GND) U1.L11(GND) U1.L13(GND) U1.M5(GND) U1.M7(GND) U1.M10(GND) U1.M12(GND) U1.M13(GND) U1.N1(GND) U1.N2(GND) U1.N3(GND) U1.N4(GND) U1.N5(GND) U1.N6(GND) U1.N12(GND) U1.N13(GND) U1.P1(GND) U1.P2(GND) U1.P3(GND) U1.P4(GND) U1.P5(GND) U1.P11(GND) U1.P12(GND) U1.P13(GND) U1.R3(GND) U1.R4(GND) U1.R5(GND) U1.R12(GND) U1.R13(GND) U1.T4(GND) U1.T5(GND) U1.T6(GND) U1.U4(GND) U1.U5(GND) U1.U6(GND) U1.U7(GND) U1.U8(GND) U1.U9(GND) U1.U10(GND) U1.U11(GND) U1.U12(GND) U1.V4(GND) U1.V5(GND) U1.V6(GND) U1.V7(GND) U1.V8(GND) U1.V9(GND) U1.V10(GND) U1.V11(GND) U1.V12(GND) U1.W4(GND) U1.W5(GND) U1.W8(GND) U1.W9(GND) U1.W10(GND) U1.W11(GND) U1.W12(GND) ; also on sheet 2 3
GND_SIGNAL: C2.1 C6.1 C17.1 C18.1 C19.1 C20.1 C21.1 C22.1 C25.1 C26.1 C27.1 C28.1 C29.1 C30.1 JP1.1 JP2.4 JP3.4 JP8.4 R22.1 R23.1 R24.1 R25.1 R28.1 R29.1 R35.2 R36.2 R40.1 R41.1 R44.1 R50.2 R51.2 R55.2 R58.2 SW4.1 U1.A14(SGND) U1.A15(SGND) U1.A16(SGND) U1.A17(SGND) U1.A18(SGND) U1.A19(SGND) U1.B14(SGND) U1.B15(SGND) U1.B16(SGND) U1.B17(SGND) U1.B18(SGND) U1.B19(SGND) U1.C14(SGND) U1.C15(SGND) U1.C16(SGND) U1.C17(SGND) U1.C18(SGND) U1.C19(SGND) U1.D14(SGND) U1.D15(SGND) U1.D16(SGND) U1.D17(SGND) U1.D18(SGND) U1.D19(SGND) U1.E14(SGND) U1.E15(SGND) U1.E16(SGND) U1.E17(SGND) U1.E18(SGND) U1.E19(SGND) U1.H14(SGND) U1.H16(SGND) U1.H17(SGND) U1.J14(SGND) U1.J15(SGND) U1.J16(SGND) U1.J18(SGND) U1.K14(SGND) U1.K16(SGND) U1.L14(SGND) U1.L15(SGND) U1.L16(SGND) U1.L17(SGND) U1.L18(SGND) U1.L19(SGND) U1.M14(SGND) U1.M15(SGND) U1.M17(SGND) U1.M18(SGND) U1.M19(SGND) U1.N14(SGND) U1.N17(SGND) U1.N18(SGND) U1.N19(SGND) U1.P14(SGND) U1.P18(SGND) U1.P19(SGND) U1.R14(SGND) U1.R15(SGND) U1.R16(SGND) U1.R17(SGND) U1.R18(SGND) U1.R19(SGND) U1.T14(SGND) U1.T15(SGND) U1.T16(SGND) U1.T17(SGND) U1.T18(SGND) U1.T19(SGND) U1.U14(SGND) U1.U15(SGND) U1.U16(SGND) U1.U17(SGND) U1.U18(SGND) U1.U19(SGND) U1.V14(SGND) U1.V15(SGND) U1.V16(SGND) U1.V17(SGND) U1.V18(SGND) U1.V19(SGND) U1.W14(SGND) U1.W15(SGND) U1.W16(SGND) U1.W17(SGND) U1.W18(SGND) U1.W19(SGND) ; also on sheet 2
VDD25: C6.2 U1.G19(VDD25) U1.H19(VDD25) ; also on sheet 2
VDD33: C2.2 R4.1 R45.2 R46.2 R47.2 R48.2 R49.2 R53.1 R54.1 R57.1 U1.J19(VDD33) ; also on sheet 2 3
VIN: C3.1 C4.1 E1.1(A) J1.1 R1.2 R2.1 R3.2 R5.2 R8.1 R9.2 R61.2 R62.2 R63.2 R64.2 ; also on sheet 2
VIN1: CIN1.2 CIN2.2 CIN3.2 CIN4.2 R1.1 R6.2 U1.A13(VIN) U1.B13(VIN) U1.C13(VIN) U1.D7(VIN) U1.D8(VIN) U1.D9(VIN) U1.D10(VIN) U1.D11(VIN) U1.D12(VIN) U1.D13(VIN) U1.E8(VIN) U1.H6(VIN) U1.J5(VIN) U1.J6(VIN) U1.L5(VIN) U1.L6(VIN) U1.M6(VIN) U1.R10(VIN) U1.T7(VIN) U1.T8(VIN) U1.T9(VIN) U1.T10(VIN) U1.T11(VIN) U1.T12(VIN) U1.T13(VIN) U1.U13(VIN) U1.V13(VIN) U1.W13(VIN)
VIN_D: C8.2 E3.1(A) R2.2 R4.2 U1.H18(VIN_D) ; also on sheet 2
VIN_SNS: C11.2 C13.1 C14.1 R3.1 R7.2 U1.K18(VIN_SNS) ; also on sheet 3
ALERTB: R47.1 U1.F13(ALERTB) ; also on sheet 2 3
AUXFAULTB: U1.K17(AUXFAULTB) ; also on sheet 2 3
CLKOUT0: E12.1(A) U1.E10(CLKOUT0) ; also on sheet 2
CLKOUT3: E13.1(A) U1.P6(CLKOUT3) ; also on sheet 2
COMP0: C19.2 R16.2 R18.1 U1.H10(COMP0a) ; also on sheet 2
COMP1: C25.2 U1.J11(COMP1) ; also on sheet 2
COMP2: C26.2 U1.M11(COMP2) ; also on sheet 2
COMP3: C20.2 R17.2 R19.2 U1.N9(COMP3a) ; also on sheet 2
CONTROL0: U1.G13(CONTROL0) ; also on sheet 3
CONTROL1: U1.G14(CONTROL1) ; also on sheet 3
CONTROL2: U1.G17(CONTROL2) ; also on sheet 3
CONTROL3: U1.F17(CONTROL3) ; also on sheet 3
FAULTB0: U1.G16(FAULTB0) ; also on sheet 2 3
FAULTB1: U1.F16(FAULTB1) ; also on sheet 2 3
FB0: C16.2 R13.1 R52.2 U1.G9(FB0) ; also on sheet 2
FB1: C23.2 R35.1 R56.2 U1.H9(FB1) ; also on sheet 2
FB2: C24.2 R36.1 R59.2 U1.M9(FB2) ; also on sheet 2
FB3: C15.2 R14.1 R60.2 U1.N10(FB3) ; also on sheet 2
HEATER: TP8.1(A) U1.K19(HEATER)
INTVCC0: C12.2 R26.1 R30.1 U1.E7(INTVCC0) ; also on sheet 2
INTVCC3: C1.2 R27.1 R31.1 U1.R11(INTVCC3) ; also on sheet 2
INTVCC12: C5.2 JP3.6 R42.1 R43.1 U1.K9(INTVCC12) ; also on sheet 2
MODE/CLKIN3: JP2.1 JP2.3 U1.R8(MODE/CLKIN3) ; also on sheet 2
MODE/CLKIN12: JP3.1 JP3.3 JP3.5 U1.L9(MODE/CLKIN12) ; also on sheet 2
PGOOD0: E10.1(A) R26.2 U1.E11(PGOOD0) ; also on sheet 2 3
PGOOD1: E22.1(A) R42.2 U1.H8(PGOOD1) ; also on sheet 2 3
PGOOD2: E23.1(A) R43.2 U1.M8(PGOOD2) ; also on sheet 2 3
PGOOD3: E11.1(A) R27.2 U1.R7(PGOOD3) ; also on sheet 2 3
PWRGD: R54.2 U1.F19(PWRGD) ; also on sheet 2 3
RUN0: E25.1(A) R61.1 R136.2 U1.F11(RUN0) ; also on sheet 2
RUN1: E26.1(A) R62.1 R137.2 U1.J8(RUN1) ; also on sheet 2
RUN2: E27.1(A) R63.1 R138.2 U1.L8(RUN2) ; also on sheet 2
RUN3: E28.1(A) R64.1 R139.2 U1.P7(RUN3) ; also on sheet 2
SCL: R49.1 U1.F14(SCL) ; also on sheet 2 3
SDA: R48.1 U1.F15(SDA) ; also on sheet 2 3
SHARE_CLK: R46.1 U1.F18(SHARE_CLK) ; also on sheet 2 3
TRACK/SS0: C21.2 R20.2 R22.2 U1.F9(TRACK/SS0) ; also on sheet 2
TRACK/SS1: C27.2 R38.2 R40.2 U1.G7(TRACK/SS1) ; also on sheet 2
TRACK/SS2: C28.2 R39.2 R41.2 U1.N7(TRACK/SS2) ; also on sheet 2
TRACK/SS3: C22.2 R21.2 R25.2 U1.P9(TRACK/SS3) ; also on sheet 2
VDAC0: R52.1 U1.P15(VDAC0)
VDAC1: R56.1 U1.N15(VDAC1)
VDAC2: R59.1 U1.M16(VDAC2)
VDAC3: R60.1 U1.P17(VDAC3)
VOSNS0+: C16.1 E4.1(A) R10.1 U1.G8(VOSNS0+) ; also on sheet 2
VOSNS0-: E7.1(A) R12.2 R13.2 U1.F8(VOSNS0-) ; also on sheet 2
VOSNS1+: C23.1 R32.1 U1.J10(VOSNS1+) ; also on sheet 2
VOSNS1-: R34.2 U1.J12(VOSNS1-) ; also on sheet 2
VOSNS2+: C24.1 R33.1 U1.L10(VOSNS2+) ; also on sheet 2
VOSNS2-: R37.2 U1.L12(VOSNS2-) ; also on sheet 2
VOSNS3+: C15.1 E5.1(A) R11.1 U1.N11(VOSNS3+) ; also on sheet 2
VOSNS3-: E8.1(A) R14.2 R15.2 U1.P10(VOSNS3-) ; also on sheet 2
VOUT0: COUT1.1 COUT2.1 COUT3.1 COUT7.1 J3.1 R10.2 U1.A1(VOUT0) U1.A2(VOUT0) U1.A3(VOUT0) U1.B1(VOUT0) U1.B2(VOUT0) U1.B3(VOUT0) U1.C1(VOUT0) U1.C2(VOUT0) U1.C3(VOUT0) U1.D1(VOUT0) U1.D2(VOUT0) U1.D3(VOUT0) U1.E1(VOUT0) U1.E2(VOUT0) ; also on sheet 2
VOUT1: COUT9.1 COUT10.1 COUT11.1 COUT12.1 E16.1 R32.2 U1.H1(VOUT1) U1.H2(VOUT1) U1.H3(VOUT1) U1.H4(VOUT1) U1.J1(VOUT1) U1.J2(VOUT1) U1.J3(VOUT1) U1.J4(VOUT1) ; also on sheet 2
VOUT2: COUT13.1 COUT14.1 COUT15.1 COUT16.1 E17.1 R33.2 U1.L1(VOUT2) U1.L2(VOUT2) U1.L3(VOUT2) U1.L4(VOUT2) U1.M1(VOUT2) U1.M2(VOUT2) U1.M3(VOUT2) U1.M4(VOUT2) ; also on sheet 2
VOUT3: COUT4.1 COUT5.1 COUT6.1 COUT8.1 J4.1 R11.2 U1.R1(VOUT3) U1.R2(VOUT3) U1.T1(VOUT3) U1.T2(VOUT3) U1.T3(VOUT3) U1.U1(VOUT3) U1.U2(VOUT3) U1.U3(VOUT3) U1.V1(VOUT3) U1.V2(VOUT3) U1.V3(VOUT3) U1.W1(VOUT3) U1.W2(VOUT3) U1.W3(VOUT3) ; also on sheet 2
WDI/RESETB: C30.2 SW4.2 U1.G18(WDI/RESETB) ; also on sheet 3
N19932056: C10.2 R9.1 U1.R9(SVIN3)
N19945980: C9.2 R8.2 U1.E9(SVIN0)
N19992814: R18.2 U1.H11(COMP0b)
N19995344: R23.2 U1.F10(FREQ0)
N19997083: R28.2 R30.2 U1.E6(PHMODE0)
N20000547: JP8.1 JP8.3 U1.G11(MODE/CLKIN0)
N20000625: E14.1(A) JP8.2
N20013058: E6.1(A) R20.1
N20013085: C17.2 R16.1
N20015200: E20.1(A) R38.1
N20015901: R44.2 U1.K10(FREQ12)
N20034973: R57.2 R58.1 U1.K15(ASEL1)
N20044502: JP1.2 U1.G15(WP)
N20044528: JP1.3 R45.1
N20045542: R53.2 R55.1 U1.H13(ASEL0)
N20079013: C18.2 R17.1
N20080322: R19.1 U1.N8(COMP3b)
N20080590: E9.1(A) R21.1
N20082543: R24.2 U1.P8(FREQ3)
N20086593: R29.2 R31.2 U1.R6(PHMODE3)
N20090384: E15.1(A) JP2.2
N20133173: E21.1(A) R39.1
N20135042: C29.2 TP1.1(A) U1.K8(TMON)
N20145686: E24.1(A) JP3.2
N20194182: R50.1 TP3.1(A) U1.A6(TSENSE0-)
N20194250: TP5.1(A) U1.H15(TSENSE2)
N20196427: R51.1 TP7.1(A) U1.W7(TSENSE3-)
N20325355: TP2.1(A) U1.A7(TSENSE0+)
N20325364: TP4.1(A) U1.J17(TSENSE1)
N20325367: TP6.1(A) U1.W6(TSENSE3+)
N20582868: C7.2 C13.2 R5.1 U1.N16(IIN_SNSP)
N20582887: C7.1 C14.2 R6.1 U1.P16(IIN_SNSM)

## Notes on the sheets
sheet 1
- REVISION HISTORY
- ECO
- REV
- DESCRIPTION
- APPROVED
- DATE
- *Note 1: Operating at low Vin range: 3.6V<Vin<4.5V
- Remove R2 and stuff R4 and R77 with zero ohm resistors and place JP9 to the "ON" position.
- 2
- PROD
- GL
- 11-15-21
- 3.6V - 15V*
- 1V / 12A
- 0.9V / 12A
- 7343
- 7343
- 1.2V / 5A
- 1.8V / 5A
- WDI/RESETB
- RESET
